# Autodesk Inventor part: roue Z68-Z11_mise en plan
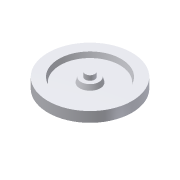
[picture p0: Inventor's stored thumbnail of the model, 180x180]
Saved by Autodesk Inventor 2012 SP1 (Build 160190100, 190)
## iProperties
Created: 2011-10
Part Number: roue Z68-Z11_mise en plan
Document SubType Name: Modeling
Designer: Bruno
Material: Par défaut
Mass: 26.9904 g
Surface Area: 107.706 cm^2
Volume: 26.9904 cm^3
Density: 1 g/cm^3
Author: Bruno
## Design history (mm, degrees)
feature "Base1"
sketch "Esquisse1"
  geometry: C1 r 26 at (0, 0) reference; C2 r 34 at (0, 0)
  constraints: 1 centre point, 1 coincident
  dimensions: "d0" = 68 diameter of C2
feature "SrfExtrusion1" sketch "Esquisse1" dims "d1" = 8, "d2" = 0
sketch "Esquisse2"
  geometry: C1 r 5.5 at (0, 0) reference; C2 r 5.5 at (0, 0)
  constraints: 1 centre point, 1 coincident
  dimensions: "d3" = 11 diameter of C2
feature "SrfExtrusion2" sketch "Esquisse2" dims "d4" = 8, "d5" = 0, "d6" = 0.5, "d7" = 0
node "Solide1"
node "Corps solides"
node "Corps surfaciques"
body "Srf1"
body "Srf2"
